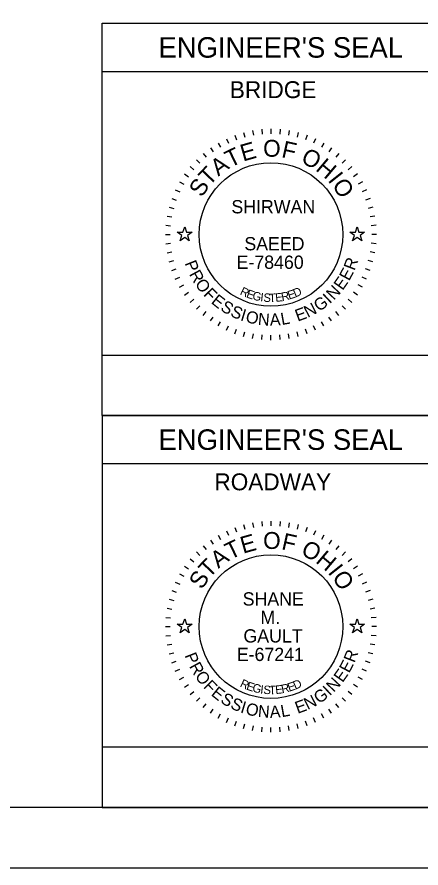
# Model space of a CAD drawing. Extents: x 0 to 34, y 0 to 22.
# Drawn here: x 6.64 to 9.99, y 0 to 7.05 of the extents above; entities that cross this region are included whole.
import ezdxf

# ---------------------------------------------------------------- set-up
doc = ezdxf.new("R2010")
doc.units = 0
for name, color, linetype in [('Default', 7, 'Continuous'), ('SH_Border', 7, 'Continuous'), ('SH_Cut_Line', 7, 'Continuous'), ('SH_Data', 7, 'Continuous')]:
    doc.layers.add(name, color=color, linetype=linetype)

msp = doc.modelspace()

# ---------------------------------------------------------------- linework, layer by layer
at = {"layer": 'Default'}
for points in [[(7.9736, 5.27), (8.0205, 5.27), (8.035, 5.3145), (8.0495, 5.27), (8.0964, 5.27), (8.0585, 5.2424), (8.073, 5.1978), (8.035, 5.2254), (7.997, 5.1978), (8.0115, 5.2424)], [(9.4036, 5.27), (9.4505, 5.27), (9.465, 5.3145), (9.4795, 5.27), (9.5264, 5.27), (9.4885, 5.2424), (9.503, 5.1978), (9.465, 5.2254), (9.427, 5.1978), (9.4415, 5.2424)], [(7.9736, 2.02), (8.0205, 2.02), (8.035, 2.0645), (8.0495, 2.02), (8.0964, 2.02), (8.0585, 1.9924), (8.073, 1.9478), (8.035, 1.9754), (7.997, 1.9478), (8.0115, 1.9924)], [(9.4036, 2.02), (9.4505, 2.02), (9.465, 2.0645), (9.4795, 2.02), (9.5264, 2.02), (9.4885, 1.9924), (9.503, 1.9478), (9.465, 1.9754), (9.427, 1.9478), (9.4415, 1.9924)]]:
    msp.add_lwpolyline(points, close=True, dxfattribs=at)
at = {"layer": 'SH_Border'}
msp.add_lwpolyline([(1.5, 21.5), (33.5, 21.5), (33.5, 0.5), (1.5, 0.5)], close=True, dxfattribs=at)
at = {"layer": 'SH_Cut_Line'}
msp.add_lwpolyline([(0, 0), (34, 0), (34, 22), (0, 22)], close=True, dxfattribs=at)
at = {"layer": 'SH_Data'}
for p, q in [((7.35, 3.75), (7.35, 7)), ((7.35, 7), (10.15, 7)), ((7.35, 6.6), (10.15, 6.6)), ((8.4507, 6.0722), (8.4644, 6.0346)), ((8.5235, 6.0952), (8.5339, 6.0565)), ((8.5981, 6.1117), (8.605, 6.0723)), ((8.6737, 6.1217), (8.6772, 6.0818)), ((8.75, 6.125), (8.75, 6.085)), ((8.8263, 6.1217), (8.8228, 6.0818)), ((8.9019, 6.1117), (8.895, 6.0723)), ((8.9765, 6.0952), (8.9661, 6.0565)), ((9.0493, 6.0722), (9.0356, 6.0346)), ((8.3125, 6.0078), (8.3325, 5.9731)), ((8.3802, 6.043), (8.3971, 6.0068)), ((9.1198, 6.043), (9.1029, 6.0068)), ((9.1875, 6.0078), (9.1675, 5.9731)), ((8.2481, 5.9668), (8.2711, 5.934)), ((9.2519, 5.9668), (9.2289, 5.934)), ((8.1313, 5.8687), (8.1596, 5.8404)), ((8.1876, 5.9203), (8.2133, 5.8896)), ((9.3124, 5.9203), (9.2867, 5.8896)), ((9.3687, 5.8687), (9.3404, 5.8404)), ((8.0797, 5.8124), (8.1104, 5.7867)), ((9.4203, 5.8124), (9.3896, 5.7867)), ((8.0332, 5.7519), (8.066, 5.7289)), ((9.4668, 5.7519), (9.434, 5.7289)), ((7.9922, 5.6875), (8.0269, 5.6675)), ((9.5078, 5.6875), (9.4731, 5.6675)), ((7.957, 5.6198), (7.9932, 5.6029)), ((9.543, 5.6198), (9.5068, 5.6029)), ((7.9278, 5.5493), (7.9654, 5.5356)), ((9.5722, 5.5493), (9.5346, 5.5356)), ((7.9048, 5.4765), (7.9435, 5.4661)), ((9.5952, 5.4765), (9.5565, 5.4661)), ((7.8883, 5.4019), (7.9277, 5.395)), ((9.6117, 5.4019), (9.5723, 5.395)), ((7.8783, 5.3263), (7.9182, 5.3228)), ((9.6217, 5.3263), (9.5818, 5.3228)), ((7.875, 5.25), (7.915, 5.25)), ((9.625, 5.25), (9.585, 5.25)), ((7.8783, 5.1737), (7.9182, 5.1772)), ((9.6217, 5.1737), (9.5818, 5.1772)), ((7.8883, 5.0981), (7.9277, 5.105)), ((9.6117, 5.0981), (9.5723, 5.105)), ((7.9048, 5.0235), (7.9435, 5.0339)), ((9.5952, 5.0235), (9.5565, 5.0339)), ((7.9278, 4.9507), (7.9654, 4.9644)), ((9.5722, 4.9507), (9.5346, 4.9644)), ((7.957, 4.8802), (7.9932, 4.8971)), ((9.543, 4.8802), (9.5068, 4.8971)), ((7.9922, 4.8125), (8.0269, 4.8325)), ((9.5078, 4.8125), (9.4731, 4.8325)), ((8.0332, 4.7481), (8.066, 4.7711)), ((9.4668, 4.7481), (9.434, 4.7711)), ((8.0797, 4.6876), (8.1104, 4.7133)), ((8.1313, 4.6313), (8.1596, 4.6596)), ((9.3687, 4.6313), (9.3404, 4.6596)), ((9.4203, 4.6876), (9.3896, 4.7133)), ((8.1876, 4.5797), (8.2133, 4.6104)), ((9.3124, 4.5797), (9.2867, 4.6104)), ((8.2481, 4.5332), (8.2711, 4.566)), ((8.3125, 4.4922), (8.3325, 4.5269)), ((9.1875, 4.4922), (9.1675, 4.5269)), ((9.2519, 4.5332), (9.2289, 4.566)), ((8.3802, 4.457), (8.3971, 4.4932)), ((8.4507, 4.4278), (8.4644, 4.4654)), ((8.5235, 4.4048), (8.5339, 4.4435)), ((8.9765, 4.4048), (8.9661, 4.4435)), ((9.0493, 4.4278), (9.0356, 4.4654)), ((9.1198, 4.457), (9.1029, 4.4932)), ((8.5981, 4.3883), (8.605, 4.4277)), ((8.6737, 4.3783), (8.6772, 4.4182)), ((8.75, 4.375), (8.75, 4.415)), ((8.8263, 4.3783), (8.8228, 4.4182)), ((8.9019, 4.3883), (8.895, 4.4277)), ((10.15, 3.75), (7.35, 3.75)), ((7.35, 3.75), (7.35, 0.5)), ((7.35, 3.75), (10.15, 3.75)), ((10.15, 3.35), (7.35, 3.35)), ((8.4507, 2.8222), (8.4644, 2.7846)), ((8.5235, 2.8452), (8.5339, 2.8065)), ((8.5981, 2.8617), (8.605, 2.8223)), ((8.6737, 2.8717), (8.6772, 2.8318)), ((8.75, 2.875), (8.75, 2.835)), ((8.8263, 2.8717), (8.8228, 2.8318)), ((8.9019, 2.8617), (8.895, 2.8223)), ((8.9765, 2.8452), (8.9661, 2.8065)), ((9.0493, 2.8222), (9.0356, 2.7846)), ((8.3125, 2.7578), (8.3325, 2.7231)), ((8.3802, 2.793), (8.3971, 2.7568)), ((9.1198, 2.793), (9.1029, 2.7568)), ((9.1875, 2.7578), (9.1675, 2.7231)), ((8.2481, 2.7168), (8.2711, 2.684)), ((9.2519, 2.7168), (9.2289, 2.684)), ((8.1313, 2.6187), (8.1596, 2.5904)), ((8.1876, 2.6703), (8.2133, 2.6396)), ((9.3124, 2.6703), (9.2867, 2.6396)), ((9.3687, 2.6187), (9.3404, 2.5904)), ((8.0797, 2.5624), (8.1104, 2.5367)), ((9.4203, 2.5624), (9.3896, 2.5367)), ((8.0332, 2.5019), (8.066, 2.4789)), ((9.4668, 2.5019), (9.434, 2.4789)), ((7.9922, 2.4375), (8.0269, 2.4175)), ((9.5078, 2.4375), (9.4731, 2.4175)), ((7.957, 2.3698), (7.9932, 2.3529)), ((9.543, 2.3698), (9.5068, 2.3529)), ((7.9278, 2.2993), (7.9654, 2.2856)), ((9.5722, 2.2993), (9.5346, 2.2856)), ((7.9048, 2.2265), (7.9435, 2.2161)), ((9.5952, 2.2265), (9.5565, 2.2161)), ((7.8883, 2.1519), (7.9277, 2.145)), ((9.6117, 2.1519), (9.5723, 2.145)), ((7.8783, 2.0763), (7.9182, 2.0728)), ((9.6217, 2.0763), (9.5818, 2.0728)), ((7.875, 2), (7.915, 2)), ((9.625, 2), (9.585, 2)), ((7.8783, 1.9237), (7.9182, 1.9272)), ((9.6217, 1.9237), (9.5818, 1.9272)), ((7.8883, 1.8481), (7.9277, 1.855)), ((9.6117, 1.8481), (9.5723, 1.855)), ((7.9048, 1.7735), (7.9435, 1.7839)), ((9.5952, 1.7735), (9.5565, 1.7839)), ((7.9278, 1.7007), (7.9654, 1.7144)), ((9.5722, 1.7007), (9.5346, 1.7144)), ((7.957, 1.6302), (7.9932, 1.6471)), ((9.543, 1.6302), (9.5068, 1.6471)), ((7.9922, 1.5625), (8.0269, 1.5825)), ((9.5078, 1.5625), (9.4731, 1.5825)), ((8.0332, 1.4981), (8.066, 1.5211)), ((9.4668, 1.4981), (9.434, 1.5211)), ((8.0797, 1.4376), (8.1104, 1.4633)), ((9.4203, 1.4376), (9.3896, 1.4633)), ((8.1313, 1.3813), (8.1596, 1.4096)), ((8.1876, 1.3297), (8.2133, 1.3604)), ((9.3124, 1.3297), (9.2867, 1.3604)), ((9.3687, 1.3813), (9.3404, 1.4096)), ((8.2481, 1.2832), (8.2711, 1.316)), ((8.3125, 1.2422), (8.3325, 1.2769)), ((9.1875, 1.2422), (9.1675, 1.2769)), ((9.2519, 1.2832), (9.2289, 1.316)), ((8.3802, 1.207), (8.3971, 1.2432)), ((8.4507, 1.1778), (8.4644, 1.2154)), ((9.0493, 1.1778), (9.0356, 1.2154)), ((9.1198, 1.207), (9.1029, 1.2432)), ((8.5235, 1.1548), (8.5339, 1.1935)), ((8.5981, 1.1383), (8.605, 1.1777)), ((8.6737, 1.1283), (8.6772, 1.1682)), ((8.75, 1.125), (8.75, 1.165)), ((8.8263, 1.1283), (8.8228, 1.1682)), ((8.9019, 1.1383), (8.895, 1.1777)), ((8.9765, 1.1548), (8.9661, 1.1935)), ((10.15, 0.5), (7.35, 0.5))]:
    msp.add_line(p, q, dxfattribs=at)
for points in [[(7.35, 3.75), (7.35, 4.25), (10.15, 4.25), (10.15, 3.75)], [(10.15, 0.5), (10.15, 1), (7.35, 1), (7.35, 0.5)]]:
    msp.add_lwpolyline(points, close=True, dxfattribs=at)
for centre in [(8.75, 5.25), (8.75, 2)]:
    msp.add_circle(centre, 0.595, dxfattribs=at)

# ---------------------------------------------------------------- texts
for s, height, p in [("ENGINEER'S SEAL", 0.17, (7.8176, 6.715)), ('BRIDGE', 0.14, (8.409, 6.38)), ('SHIRWAN', 0.11, (8.422, 5.4249)), ('SAEED', 0.11, (8.5294, 5.1184)), ('E-78460', 0.11, (8.4649, 4.9651)), ("ENGINEER'S SEAL", 0.17, (7.8176, 3.465)), ('ROADWAY', 0.14, (8.2811, 3.13)), ('SHANE', 0.11, (8.5155, 2.1749)), ('M.', 0.11, (8.6626, 2.0216)), ('GAULT', 0.11, (8.5218, 1.8684)), ('E-67241', 0.11, (8.4667, 1.7151))]:
    msp.add_text(s, height=height, dxfattribs=at).set_placement(p)
for s, height, rotation, p in [('E', 0.14, 15.75706, (8.5184, 5.8538)), ('O', 0.14, 359.78119, (8.6847, 5.8943)), ('F', 0.14, 347.43619, (8.8311, 5.8917)), ('T', 0.14, 25.71674, (8.4116, 5.8018)), ('O', 0.14, 332.25863, (8.9898, 5.8515)), ('A', 0.14, 36.47472, (8.3134, 5.7281)), ('H', 0.14, 319.91363, (9.1132, 5.7861)), ('T', 0.14, 46.4344, (8.2383, 5.6464)), ('I', 0.14, 308.36695, (9.2165, 5.6983)), ('S', 0.14, 57.19238, (8.1781, 5.5514)), ('O', 0.14, 303.14906, (9.2521, 5.6589)), ('P', 0.1, 291.49398, (8.0323, 5.0121)), ('R', 0.1, 69.23216, (9.4419, 4.9454)), ('R', 0.1, 298.73106, (8.069, 4.9217)), ('E', 0.1, 61.99508, (9.3976, 4.8598)), ('O', 0.1, 306.46664, (8.1155, 4.8383)), ('E', 0.1, 54.75801, (9.3433, 4.7814)), ('F', 0.1, 314.7068, (8.1843, 4.7483)), ('R', 0.07, 334.48695, (8.4875, 4.7551)), ('D', 0.07, 23.30524, (8.951, 4.727)), ('N', 0.1, 47.02243, (9.2702, 4.7008)), ('E', 0.1, 321.43929, (8.2478, 4.6848)), ('E', 0.07, 341.03996, (8.5406, 4.7301)), ('G', 0.07, 347.47515, (8.5914, 4.7118)), ('I', 0.07, 353.78581, (8.6591, 4.6968)), ('S', 0.07, 356.89262, (8.6858, 4.6929)), ('T', 0.07, 3.00609, (8.7357, 4.6887)), ('E', 0.07, 6.01169, (8.7889, 4.6912)), ('R', 0.07, 11.91844, (8.8425, 4.6974)), ('E', 0.07, 17.68363, (8.8998, 4.7102)), ('G', 0.1, 35.04687, (9.1481, 4.607)), ('I', 0.1, 43.28703, (9.2368, 4.6714)), ('S', 0.1, 328.67637, (8.3243, 4.6252)), ('S', 0.1, 335.91345, (8.4064, 4.5766)), ('N', 0.1, 27.31129, (9.0545, 4.5575)), ('I', 0.1, 343.15053, (8.4906, 4.5397)), ('O', 0.1, 346.88592, (8.5339, 4.5251)), ('N', 0.1, 355.12608, (8.6388, 4.5017)), ('A', 0.1, 2.86166, (8.7423, 4.4937)), ('L', 0.1, 10.09874, (8.8394, 4.499)), ('E', 0.1, 20.07421, (8.9712, 4.527)), ('E', 0.14, 15.75706, (8.5184, 2.6038)), ('O', 0.14, 359.78119, (8.6847, 2.6443)), ('F', 0.14, 347.43619, (8.8311, 2.6417)), ('T', 0.14, 25.71674, (8.4116, 2.5518)), ('O', 0.14, 332.25863, (8.9898, 2.6015)), ('A', 0.14, 36.47472, (8.3134, 2.4781)), ('H', 0.14, 319.91363, (9.1132, 2.5361)), ('T', 0.14, 46.4344, (8.2383, 2.3964)), ('I', 0.14, 308.36695, (9.2165, 2.4483)), ('S', 0.14, 57.19238, (8.1781, 2.3014)), ('O', 0.14, 303.14906, (9.2521, 2.4089)), ('P', 0.1, 291.49398, (8.0323, 1.7621)), ('R', 0.1, 69.23216, (9.4419, 1.6954)), ('R', 0.1, 298.73106, (8.069, 1.6717)), ('E', 0.1, 61.99508, (9.3976, 1.6098)), ('O', 0.1, 306.46664, (8.1155, 1.5883)), ('E', 0.1, 54.75801, (9.3433, 1.5314)), ('F', 0.1, 314.7068, (8.1843, 1.4983)), ('R', 0.07, 334.48695, (8.4875, 1.5051)), ('D', 0.07, 23.30524, (8.951, 1.477)), ('N', 0.1, 47.02243, (9.2702, 1.4508)), ('E', 0.1, 321.43929, (8.2478, 1.4348)), ('E', 0.07, 341.03996, (8.5406, 1.4801)), ('G', 0.07, 347.47515, (8.5914, 1.4618)), ('I', 0.07, 353.78581, (8.6591, 1.4468)), ('S', 0.07, 356.89262, (8.6858, 1.4429)), ('T', 0.07, 3.00609, (8.7357, 1.4387)), ('E', 0.07, 6.01169, (8.7889, 1.4412)), ('R', 0.07, 11.91844, (8.8425, 1.4474)), ('E', 0.07, 17.68363, (8.8998, 1.4602)), ('I', 0.1, 43.28703, (9.2368, 1.4214)), ('S', 0.1, 328.67637, (8.3243, 1.3752)), ('N', 0.1, 27.31129, (9.0545, 1.3075)), ('G', 0.1, 35.04687, (9.1481, 1.357)), ('S', 0.1, 335.91345, (8.4064, 1.3266)), ('I', 0.1, 343.15053, (8.4906, 1.2897)), ('O', 0.1, 346.88592, (8.5339, 1.2751)), ('N', 0.1, 355.12608, (8.6388, 1.2517)), ('A', 0.1, 2.86166, (8.7423, 1.2437)), ('L', 0.1, 10.09874, (8.8394, 1.249)), ('E', 0.1, 20.07421, (8.9712, 1.277))]:
    msp.add_text(s, height=height, rotation=rotation, dxfattribs=at).set_placement(p)

doc.saveas('drawing.dxf')
